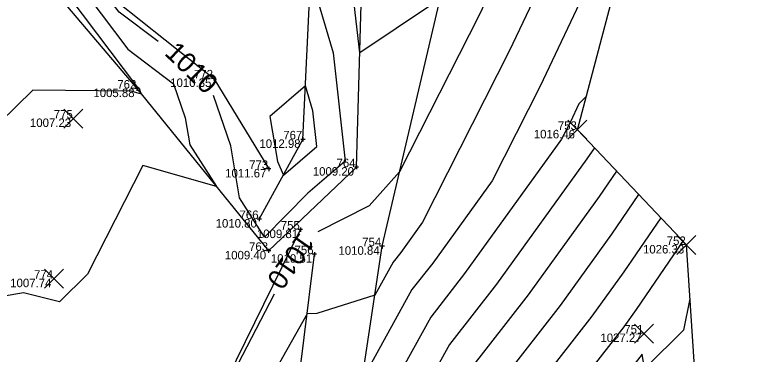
# Model space of a CAD drawing. Extents: x 2354693 to 2355622, y 637071 to 710080.
# Drawn here: x 2355430.4 to 2355533.4, y 709286.7 to 709334.6 of the extents above; entities that cross this region are included whole.
import ezdxf

# ---------------------------------------------------------------- set-up
doc = ezdxf.new("R2010")
doc.units = 0
for name, color, linetype in [('Default', 7, 'Continuous'), ('DT_X_Contour_Major', 7, 'Continuous'), ('DT_X_Contour_Minor', 7, 'Continuous'), ('SV_X_Break_Lines', 7, 'Continuous'), ('SV_X_Random_Point', 7, 'Continuous'), ('SV_X_Shot_Marker', 7, 'Continuous'), ('SV_X_Text_Elevation', 7, 'Continuous'), ('SV_X_Text_Name', 7, 'Continuous'), ('SV_X_Toe_of_Slope', 7, 'Continuous'), ('SV_X_Top_of_Bank', 7, 'Continuous')]:
    doc.layers.add(name, color=color, linetype=linetype)

msp = doc.modelspace()

# ---------------------------------------------------------------- linework, layer by layer
at = {"layer": 'Default'}
msp.add_lwpolyline([(2355263.76, 708986.4), (2355330.91, 709003.61), (2355347.35, 709002.09), (2355387.45, 709051.54), (2355402.1, 709089.16), (2355425.96, 709130.16), (2355495.56, 709194.41), (2355530.33, 709221.46), (2355525, 709302.12), (2355509.66, 709318.33), (2355534.8, 709413.26), (2355566.11, 709428.47), (2355585.74, 709473.78), (2355589.64, 709532.44), (2355608.23, 709591.27)], dxfattribs=at)
msp.add_lwpolyline([(2355263.76, 708986.4), (2355330.91, 709003.61), (2355347.35, 709002.09), (2355387.45, 709051.54), (2355402.1, 709089.16), (2355425.96, 709130.16), (2355495.56, 709194.41), (2355530.33, 709221.46), (2355525, 709302.12), (2355509.66, 709318.33), (2355534.8, 709413.26), (2355566.11, 709428.47), (2355585.74, 709473.78), (2355589.64, 709532.44), (2355608.23, 709591.27)], dxfattribs=at)
at = {"layer": 'DT_X_Contour_Major'}
for points in [[(2355527.44, 709385.48), (2355512.64, 709370.03), (2355495.83, 709334.5), (2355484.62, 709312.4), (2355480.32, 709307.64), (2355473.09, 709303.99)], [(2355527.44, 709385.48), (2355512.64, 709370.03), (2355495.83, 709334.5), (2355484.62, 709312.4), (2355480.32, 709307.64), (2355473.09, 709303.99)], [(2355443.39, 709337.22), (2355444.8, 709339.03), (2355461.03, 709346.58), (2355462.53, 709343.17), (2355469.34, 709337.47), (2355472.1, 709339.84), (2355475.25, 709329.18), (2355476.95, 709313.91), (2355471.7, 709309.42), (2355465.6, 709303.22), (2355462.07, 709308.75), (2355460.83, 709316.09), (2355458.39, 709323.15)], [(2355443.39, 709337.22), (2355444.8, 709339.03), (2355461.03, 709346.58), (2355462.53, 709343.17), (2355469.34, 709337.47), (2355472.1, 709339.84), (2355475.25, 709329.18), (2355476.95, 709313.91), (2355471.7, 709309.42), (2355465.6, 709303.22), (2355462.07, 709308.75), (2355460.83, 709316.09), (2355458.39, 709323.15)], [(2355450.6, 709330.75), (2355445.14, 709334.89), (2355443.39, 709337.22)], [(2355450.6, 709330.75), (2355445.14, 709334.89), (2355443.39, 709337.22)], [(2355515.17, 709312.51), (2355512.73, 709308.93), (2355502.73, 709295.09), (2355494.29, 709284.26), (2355477.23, 709253.42), (2355475.48, 709250.7), (2355474.67, 709248.74), (2355471.36, 709249.03), (2355465.85, 709249.25), (2355457.97, 709242.47), (2355456.56, 709237.73), (2355456.54, 709237.65)], [(2355515.17, 709312.51), (2355512.73, 709308.93), (2355502.73, 709295.09), (2355494.29, 709284.26), (2355477.23, 709253.42), (2355475.48, 709250.7), (2355474.67, 709248.74), (2355471.36, 709249.03), (2355465.85, 709249.25), (2355457.97, 709242.47), (2355456.56, 709237.73), (2355456.54, 709237.65)], [(2355466.95, 709295.19), (2355452.85, 709268.07), (2355452.66, 709267.73), (2355452.57, 709267.62), (2355452.2, 709267.46), (2355421.16, 709255.22), (2355416.53, 709254.8), (2355413.99, 709261.4), (2355405.36, 709273.14), (2355396.68, 709274.87)], [(2355466.95, 709295.19), (2355452.85, 709268.07), (2355452.66, 709267.73), (2355452.57, 709267.62), (2355452.2, 709267.46), (2355421.16, 709255.22), (2355416.53, 709254.8), (2355413.99, 709261.4), (2355405.36, 709273.14), (2355396.68, 709274.87)]]:
    msp.add_lwpolyline(points, dxfattribs=at)
at = {"layer": 'DT_X_Contour_Minor'}
for points in [[(2355511.72, 709354.01), (2355500.11, 709329.49), (2355487.86, 709305.34), (2355484.78, 709301.07), (2355483.71, 709299.69), (2355481.13, 709295.03), (2355472.96, 709292.48), (2355471.58, 709292.43), (2355455.81, 709264.49), (2355447.87, 709258.14), (2355428.41, 709239.73)], [(2355511.72, 709354.01), (2355500.11, 709329.49), (2355487.86, 709305.34), (2355484.78, 709301.07), (2355483.71, 709299.69), (2355481.13, 709295.03), (2355472.96, 709292.48), (2355471.58, 709292.43), (2355455.81, 709264.49), (2355447.87, 709258.14), (2355428.41, 709239.73)], [(2355434.3, 709342.15), (2355447.56, 709324.46), (2355447.93, 709324.18), (2355448.02, 709323.9), (2355448.06, 709323.68), (2355448.28, 709323.34), (2355446.82, 709323.76), (2355432.98, 709323.93), (2355414.16, 709305.5)], [(2355434.3, 709342.15), (2355447.56, 709324.46), (2355447.93, 709324.18), (2355448.02, 709323.9), (2355448.06, 709323.68), (2355448.28, 709323.34), (2355446.82, 709323.76), (2355432.98, 709323.93), (2355414.16, 709305.5)], [(2355438.85, 709339.69), (2355446.35, 709329.67), (2355452.76, 709324.82), (2355454.43, 709320), (2355455.07, 709316.21), (2355458.81, 709310.36), (2355448.46, 709313.29), (2355440.68, 709297.99), (2355436.71, 709294.1), (2355431.65, 709295.37), (2355417.4, 709292.87)], [(2355438.85, 709339.69), (2355446.35, 709329.67), (2355452.76, 709324.82), (2355454.43, 709320), (2355455.07, 709316.21), (2355458.81, 709310.36), (2355448.46, 709313.29), (2355440.68, 709297.99), (2355436.71, 709294.1), (2355431.65, 709295.37), (2355417.4, 709292.87)], [(2355510.79, 709337.99), (2355504.4, 709324.48), (2355497.65, 709311.17), (2355489.27, 709299.57), (2355486.35, 709295.83), (2355479.34, 709283.15), (2355473.42, 709281.3), (2355470.19, 709281.19), (2355459.02, 709261.4), (2355443.13, 709248.69), (2355434.71, 709240.72), (2355435.4, 709239.96), (2355434.45, 709233.23), (2355432.86, 709227.06), (2355429.2, 709222.75)], [(2355510.79, 709337.99), (2355504.4, 709324.48), (2355497.65, 709311.17), (2355489.27, 709299.57), (2355486.35, 709295.83), (2355479.34, 709283.15), (2355473.42, 709281.3), (2355470.19, 709281.19), (2355459.02, 709261.4), (2355443.13, 709248.69), (2355434.71, 709240.72), (2355435.4, 709239.96), (2355434.45, 709233.23), (2355432.86, 709227.06), (2355429.2, 709222.75)], [(2355489.24, 709336.03), (2355479, 709329.17), (2355478.08, 709337.35)], [(2355489.24, 709336.03), (2355479, 709329.17), (2355478.08, 709337.35)], [(2355472.41, 709321.01), (2355471.37, 709324.52), (2355466.32, 709320.19), (2355467.4, 709313.87), (2355468.25, 709311.95), (2355472.97, 709315.98), (2355472.41, 709321.01)], [(2355472.41, 709321.01), (2355471.37, 709324.52), (2355466.32, 709320.19), (2355467.4, 709313.87), (2355468.25, 709311.95), (2355472.97, 709315.98), (2355472.41, 709321.01)], [(2355510.91, 709323.07), (2355509.87, 709321.98), (2355508.68, 709319.47), (2355507.43, 709317), (2355493.75, 709298.08), (2355489, 709291.97), (2355477.54, 709271.27), (2355473.88, 709270.13), (2355468.81, 709269.95), (2355462.23, 709258.3), (2355443.4, 709243.24), (2355441.47, 709241.59), (2355440.08, 709236.93), (2355439.04, 709229.6), (2355438.39, 709227.08), (2355441.03, 709225.48), (2355439.54, 709219.65), (2355433.91, 709212.05), (2355427.03, 709199.09)], [(2355510.91, 709323.07), (2355509.87, 709321.98), (2355508.68, 709319.47), (2355507.43, 709317), (2355493.75, 709298.08), (2355489, 709291.97), (2355477.54, 709271.27), (2355473.88, 709270.13), (2355468.81, 709269.95), (2355462.23, 709258.3), (2355443.4, 709243.24), (2355441.47, 709241.59), (2355440.08, 709236.93), (2355439.04, 709229.6), (2355438.39, 709227.08), (2355441.03, 709225.48), (2355439.54, 709219.65), (2355433.91, 709212.05), (2355427.03, 709199.09)], [(2355512.06, 709315.8), (2355511, 709314.24), (2355498.24, 709296.58), (2355491.64, 709288.12), (2355475.75, 709259.39), (2355474.35, 709258.95), (2355467.42, 709258.71), (2355465.44, 709255.21), (2355459.78, 709250.68), (2355449.72, 709242.03), (2355446.52, 709231.3), (2355446.05, 709228.22), (2355446.84, 709227.3), (2355450.15, 709225.3), (2355446.88, 709212.49), (2355443.99, 709208.59), (2355440.46, 709201.95), (2355441.77, 709200.32), (2355421.1, 709181.12)], [(2355512.06, 709315.8), (2355511, 709314.24), (2355498.24, 709296.58), (2355491.64, 709288.12), (2355475.75, 709259.39), (2355474.35, 709258.95), (2355467.42, 709258.71), (2355465.44, 709255.21), (2355459.78, 709250.68), (2355449.72, 709242.03), (2355446.52, 709231.3), (2355446.05, 709228.22), (2355446.84, 709227.3), (2355450.15, 709225.3), (2355446.88, 709212.49), (2355443.99, 709208.59), (2355440.46, 709201.95), (2355441.77, 709200.32), (2355421.1, 709181.12)], [(2355518.27, 709309.23), (2355514.46, 709303.63), (2355507.21, 709293.59), (2355496.93, 709280.4), (2355484.12, 709257.23), (2355477.7, 709247.29), (2355474.77, 709240.12), (2355466.09, 709240.88), (2355464.34, 709229.47), (2355468.12, 709225.09), (2355468.38, 709224.93), (2355467.59, 709221.81), (2355462.23, 709207.44), (2355459.02, 709203.82), (2355455.82, 709201.52), (2355428.34, 709177.87)], [(2355518.27, 709309.23), (2355514.46, 709303.63), (2355507.21, 709293.59), (2355496.93, 709280.4), (2355484.12, 709257.23), (2355477.7, 709247.29), (2355474.77, 709240.12), (2355466.09, 709240.88), (2355464.34, 709229.47), (2355468.12, 709225.09), (2355468.38, 709224.93), (2355467.59, 709221.81), (2355462.23, 709207.44), (2355459.02, 709203.82), (2355455.82, 709201.52), (2355428.34, 709177.87)], [(2355521.38, 709305.94), (2355516.2, 709298.32), (2355511.7, 709292.09), (2355499.57, 709276.54), (2355491.01, 709261.05), (2355479.93, 709243.88), (2355474.87, 709231.51), (2355473.72, 709231.61), (2355473.49, 709230.09), (2355474.12, 709229.36), (2355473.63, 709226.98), (2355476.06, 709226.81), (2355475.08, 709222.95), (2355470.27, 709210.06), (2355463.67, 709202.62), (2355457.1, 709197.88), (2355434.77, 709178.67), (2355427.81, 709161.59)], [(2355521.38, 709305.94), (2355516.2, 709298.32), (2355511.7, 709292.09), (2355499.57, 709276.54), (2355491.01, 709261.05), (2355479.93, 709243.88), (2355474.87, 709231.51), (2355473.72, 709231.61), (2355473.49, 709230.09), (2355474.12, 709229.36), (2355473.63, 709226.98), (2355476.06, 709226.81), (2355475.08, 709222.95), (2355470.27, 709210.06), (2355463.67, 709202.62), (2355457.1, 709197.88), (2355434.77, 709178.67), (2355427.81, 709161.59)], [(2355524.49, 709302.66), (2355517.93, 709293.02), (2355516.18, 709290.6), (2355502.22, 709272.68), (2355497.89, 709264.86), (2355482.16, 709240.47), (2355478.46, 709231.43), (2355478.07, 709229.49), (2355483.44, 709229.13), (2355481.26, 709220.6), (2355478.31, 709212.69), (2355468.33, 709201.42), (2355458.38, 709194.25), (2355441.2, 709179.47), (2355435.74, 709166.06), (2355427.13, 709148.41)], [(2355524.49, 709302.66), (2355517.93, 709293.02), (2355516.18, 709290.6), (2355502.22, 709272.68), (2355497.89, 709264.86), (2355482.16, 709240.47), (2355478.46, 709231.43), (2355478.07, 709229.49), (2355483.44, 709229.13), (2355481.26, 709220.6), (2355478.31, 709212.69), (2355468.33, 709201.42), (2355458.38, 709194.25), (2355441.2, 709179.47), (2355435.74, 709166.06), (2355427.13, 709148.41)], [(2355525.5, 709294.55), (2355524.58, 709290.12), (2355519.34, 709284.91), (2355519.01, 709285.31), (2355518.76, 709286.73), (2355505.62, 709269.79), (2355504.86, 709268.82), (2355504.78, 709268.67), (2355484.39, 709237.07), (2355482.68, 709232.9), (2355482.5, 709232.01), (2355490.82, 709231.44), (2355487.45, 709218.24), (2355486.35, 709215.31), (2355472.99, 709200.22), (2355459.66, 709190.62), (2355447.63, 709180.27), (2355443.81, 709170.88), (2355426.26, 709134.89)], [(2355525.5, 709294.55), (2355524.58, 709290.12), (2355519.34, 709284.91), (2355519.01, 709285.31), (2355518.76, 709286.73), (2355505.62, 709269.79), (2355504.86, 709268.82), (2355504.78, 709268.67), (2355484.39, 709237.07), (2355482.68, 709232.9), (2355482.5, 709232.01), (2355490.82, 709231.44), (2355487.45, 709218.24), (2355486.35, 709215.31), (2355472.99, 709200.22), (2355459.66, 709190.62), (2355447.63, 709180.27), (2355443.81, 709170.88), (2355426.26, 709134.89)]]:
    msp.add_lwpolyline(points, dxfattribs=at)
at = {"layer": 'SV_X_Break_Lines'}
msp.add_lwpolyline([(2355425.79, 709239.32), (2355452.61, 709267.58), (2355470.64, 709304.29)], dxfattribs=at)
at = {"layer": 'SV_X_Random_Point'}
for p, q in [((2355437.34, 709318.59), (2355440, 709321.26)), ((2355437.34, 709321.26), (2355440, 709318.59)), ((2355508.32, 709317), (2355510.99, 709319.67)), ((2355508.32, 709319.67), (2355510.99, 709317)), ((2355523.67, 709300.78), (2355526.33, 709303.45)), ((2355523.67, 709303.45), (2355526.33, 709300.78)), ((2355434.62, 709296.04), (2355437.29, 709298.71)), ((2355434.62, 709298.71), (2355437.29, 709296.04)), ((2355517.7, 709288.31), (2355520.36, 709290.98)), ((2355517.7, 709290.98), (2355520.36, 709288.31))]:
    msp.add_line(p, q, dxfattribs=at)
at = {"layer": 'SV_X_Shot_Marker'}
for p, q in [((2355458.73, 709325.57), (2355458.13, 709325.57)), ((2355458.43, 709325.87), (2355458.43, 709325.27)), ((2355447.93, 709324.14), (2355447.33, 709324.14)), ((2355447.63, 709324.44), (2355447.63, 709323.84)), ((2355471.31, 709316.99), (2355470.71, 709316.99)), ((2355471.01, 709317.29), (2355471.01, 709316.69)), ((2355466.49, 709312.83), (2355465.89, 709312.83)), ((2355466.19, 709313.13), (2355466.19, 709312.53)), ((2355478.84, 709313.08), (2355478.24, 709313.08)), ((2355478.54, 709313.38), (2355478.54, 709312.78)), ((2355465.16, 709305.77), (2355464.56, 709305.77)), ((2355464.86, 709306.07), (2355464.86, 709305.47)), ((2355470.64, 709304.59), (2355470.64, 709303.99)), ((2355470.94, 709304.29), (2355470.34, 709304.29)), ((2355466.46, 709301.29), (2355465.86, 709301.29)), ((2355466.16, 709301.59), (2355466.16, 709300.99)), ((2355482.47, 709301.94), (2355481.87, 709301.94)), ((2355482.17, 709302.24), (2355482.17, 709301.64)), ((2355472.91, 709300.82), (2355472.31, 709300.82)), ((2355472.61, 709301.12), (2355472.61, 709300.52))]:
    msp.add_line(p, q, dxfattribs=at)
at = {"layer": 'SV_X_Toe_of_Slope'}
for points in [[(2355479.39, 709341.77), (2355467.9, 709354.41), (2355445.71, 709358.38), (2355430.69, 709344.11), (2355447.63, 709324.14), (2355466.16, 709301.29), (2355478.54, 709313.08), (2355479.33, 709340.95)], [(2355474.64, 709251.99), (2355482.17, 709301.94), (2355491.1, 709340.03)]]:
    msp.add_lwpolyline(points, dxfattribs=at)
at = {"layer": 'SV_X_Top_of_Bank'}
for points in [[(2355464.86, 709305.77), (2355471.01, 709316.99), (2355472.13, 709340.52), (2355463.72, 709348.25), (2355444.88, 709347.02), (2355444.77, 709336.47), (2355458.43, 709325.57), (2355466.19, 709312.83)], [(2355514.82, 709244.93), (2355486.29, 709234.15), (2355474.89, 709230.19), (2355441.2, 709227.89), (2355439.52, 709241.48), (2355464.49, 709242.82), (2355466.82, 709253.88), (2355472.61, 709300.82)]]:
    msp.add_lwpolyline(points, dxfattribs=at)

# ---------------------------------------------------------------- texts
at = {"layer": 'DT_X_Contour_Major'}
for rotation, p in [(315.6944, (2355451.38, 709329)), (315.6944, (2355451.38, 709329)), (235.1254, (2355470.55, 709304.05)), (235.1254, (2355470.55, 709304.05))]:
    msp.add_text('1010', height=2.8, rotation=rotation, dxfattribs=at).set_placement(p)
at = {"layer": 'SV_X_Text_Elevation'}
for s, p in [('1010.35', (2355452.31, 709324.37)), ('1005.88', (2355441.49, 709322.94)), ('1007.23', (2355432.56, 709318.73)), ('1016.46', (2355503.51, 709317.13)), ('1012.98', (2355464.87, 709315.79)), ('1011.67', (2355460.05, 709311.63)), ('1009.20', (2355472.39, 709311.88)), ('1010.80', (2355458.71, 709304.57)), ('1009.81', (2355464.52, 709303.09)), ('1009.40', (2355460.01, 709300.09)), ('1010.84', (2355476, 709300.74)), ('1026.33', (2355518.89, 709300.92)), ('1010.51', (2355466.49, 709299.62)), ('1007.74', (2355429.78, 709296.17)), ('1027.27', (2355512.89, 709288.45))]:
    msp.add_text(s, height=1.2, dxfattribs=at).set_placement(p)
at = {"layer": 'SV_X_Text_Name'}
for s, p in [('772', (2355455.66, 709325.57)), ('762', (2355444.86, 709324.14)), ('775', (2355435.91, 709319.93)), ('753', (2355506.9, 709318.33)), ('767', (2355468.23, 709316.99)), ('773', (2355463.43, 709312.83)), ('764', (2355475.73, 709313.08)), ('766', (2355462.07, 709305.77)), ('755', (2355467.88, 709304.29)), ('763', (2355463.41, 709301.29)), ('754', (2355479.35, 709301.94)), ('752', (2355522.23, 709302.12)), ('756', (2355469.82, 709300.82)), ('774', (2355433.13, 709297.37)), ('751', (2355516.26, 709289.65))]:
    msp.add_text(s, height=1.2, dxfattribs=at).set_placement(p)

doc.saveas('drawing.dxf')
